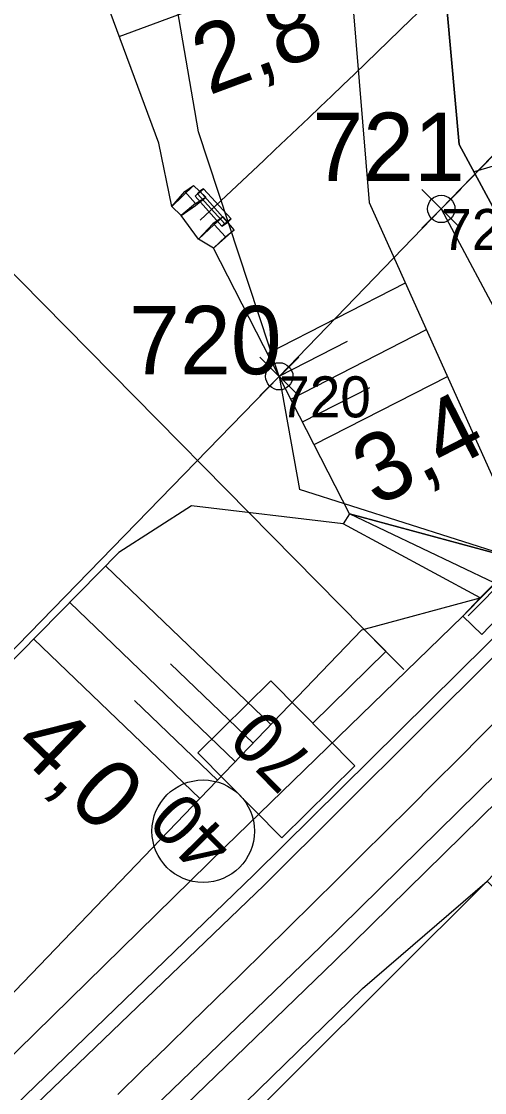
# Model space of a CAD drawing. Extents: x -800194 to -799078, y -1007177 to -1006597.
# Drawn here: x -799442.55 to -799428.99, y -1006906.14 to -1006874.78 of the extents above; entities that cross this region are included whole.
import ezdxf

# ---------------------------------------------------------------- set-up
doc = ezdxf.new("R2010")
doc.units = 0
for name, color, linetype in [('02_Osa_koleje', 7, 'Continuous'), ('Obvod stavby', 7, 'Continuous'), ('Vrstva 12', 7, 'Continuous'), ('Vrstva 17', 7, 'Continuous'), ('Vrstva 18', 7, 'Continuous'), ('Vrstva 23', 7, 'Continuous'), ('Vrstva 4', 7, 'Continuous'), ('Vrstva 47', 7, 'Continuous'), ('Vrstva 48', 7, 'Continuous'), ('Vrstva 49', 7, 'Continuous'), ('Vrstva 5', 7, 'Continuous'), ('Vrstva 50', 7, 'Continuous'), ('Vrstva 53', 7, 'Continuous'), ('Vrstva 55', 7, 'Continuous'), ('Vrstva 56', 7, 'Continuous'), ('Vrstva 60', 7, 'Continuous')]:
    doc.layers.add(name, color=color, linetype=linetype)

msp = doc.modelspace()

# ---------------------------------------------------------------- linework, layer by layer
at = {"layer": '02_Osa_koleje'}
msp.add_lwpolyline([(-799428.348, -1006894.948), (-799429.054, -1006895.657), (-799429.76, -1006896.365), (-799430.467, -1006897.072), (-799431.174, -1006897.779), (-799431.883, -1006898.484), (-799432.592, -1006899.19), (-799433.302, -1006899.894), (-799434.012, -1006900.598), (-799434.724, -1006901.3), (-799435.436, -1006902.002), (-799436.149, -1006902.703), (-799436.864, -1006903.403), (-799437.579, -1006904.102), (-799438.295, -1006904.8), (-799439.012, -1006905.497), (-799439.73, -1006906.193)], dxfattribs=at)
at = {"layer": 'Obvod stavby'}
for p, q in [((-799430.826, -1006880.836), (-799429.694, -1006879.704)), ((-799430.826, -1006879.704), (-799429.694, -1006880.836)), ((-799435.566, -1006885.736), (-799434.434, -1006884.604)), ((-799435.566, -1006884.604), (-799434.434, -1006885.736))]:
    msp.add_line(p, q, dxfattribs=at)
msp.add_lwpolyline([(-799559.64, -1006968.48), (-799519.68, -1006952.01), (-799500.87, -1006940.41), (-799496.64, -1006937.8), (-799494.85, -1006936.7), (-799484.52, -1006930.32), (-799457.99, -1006908.8), (-799435, -1006885.17), (-799430.26, -1006880.27), (-799425.53, -1006875.38), (-799422.55, -1006864.36), (-799416.748, -1006858.798), (-799395.763, -1006879.374), (-799413.75, -1006898.23), (-799418.41, -1006902.53), (-799423.07, -1006906.83), (-799433.4, -1006916.39), (-799469.5, -1006946.86), (-799487.22, -1006958.47), (-799495.25, -1006963.74), (-799521.98, -1006977.8), (-799546.71, -1006987.83)], dxfattribs=at)
for centre in [(-799430.26, -1006880.27), (-799435, -1006885.17)]:
    msp.add_circle(centre, 0.4, dxfattribs=at)
at = {"layer": 'Vrstva 12'}
for p, q in [((-799437.769, -1006879.761), (-799437.512, -1006879.586)), ((-799437.452, -1006880.113), (-799437.147, -1006879.929)), ((-799436.644, -1006880.497), (-799436.908, -1006880.728)), ((-799436.578, -1006881.084), (-799436.322, -1006880.878))]:
    msp.add_line(p, q, dxfattribs=at)
for points in [[(-799437.876, -1006880.464), (-799437.451, -1006880.166), (-799437.147, -1006879.929), (-799437.512, -1006879.586), (-799438.146, -1006880.193)], [(-799437.876, -1006880.464), (-799438.146, -1006880.193), (-799437.769, -1006879.761), (-799437.452, -1006880.113), (-799437.876, -1006880.464)], [(-799436.923, -1006881.42), (-799436.322, -1006880.878), (-799436.644, -1006880.497), (-799436.942, -1006880.704), (-799437.363, -1006881.152)], [(-799437.363, -1006881.152), (-799436.908, -1006880.728), (-799436.578, -1006881.084), (-799436.923, -1006881.42), (-799437.363, -1006881.152)]]:
    msp.add_lwpolyline(points, dxfattribs=at)
at = {"layer": 'Vrstva 17'}
msp.add_line((-799429.476, -1006892.183), (-799417.039, -1006879.551), dxfattribs=at)
at = {"layer": 'Vrstva 18'}
msp.add_line((-799429.125, -1006891.656), (-799433.133, -1006889.484), dxfattribs=at)
for points in [[(-799429.627, -1006892.19), (-799429.629, -1006892.192), (-799429.125, -1006891.656), (-799428.698, -1006891.23), (-799418.02, -1006880.424), (-799417.6, -1006879.987), (-799417.085, -1006879.46), (-799417.085, -1006879.46)], [(-799429.07, -1006892.727), (-799423.479, -1006886.901), (-799416.56, -1006880.007), (-799417.085, -1006879.46), (-799429.627, -1006892.19), (-799429.07, -1006892.727)], [(-799428.698, -1006891.23), (-799432.944, -1006889.197), (-799433.133, -1006889.484)], [(-799432.944, -1006889.197), (-799427.892, -1006890.566), (-799428.698, -1006891.23)], [(-799429.07, -1006892.727), (-799429.629, -1006892.192)]]:
    msp.add_lwpolyline(points, dxfattribs=at)
at = {"layer": 'Vrstva 23'}
for p, q in [((-799437.219, -1006879.681), (-799436.41, -1006880.559)), ((-799436.679, -1006880.778), (-799437.467, -1006879.896)), ((-799437.399, -1006879.826), (-799436.594, -1006880.708)), ((-799437.328, -1006879.75), (-799436.517, -1006880.669))]:
    msp.add_line(p, q, dxfattribs=at)
for points in [[(-799437.467, -1006879.896), (-799437.399, -1006879.826), (-799437.219, -1006879.681), (-799437.328, -1006879.75), (-799437.467, -1006879.896)], [(-799436.517, -1006880.669), (-799436.41, -1006880.559), (-799436.594, -1006880.708), (-799436.679, -1006880.778), (-799436.517, -1006880.669)]]:
    msp.add_lwpolyline(points, dxfattribs=at)
at = {"layer": 'Vrstva 4'}
for points in [[(-799510.394, -1006958.536), (-799498.027, -1006951.328), (-799477.988, -1006937.435), (-799460.33, -1006923.117), (-799451.862, -1006915.581), (-799443.604, -1006907.9), (-799435.444, -1006900.067), (-799428.64, -1006893.299), (-799422.817, -1006887.511), (-799415.998, -1006880.595), (-799408.158, -1006872.652), (-799401.02, -1006864.85)], [(-799509.248, -1006960.724), (-799497.456, -1006953.809), (-799476.495, -1006939.437), (-799458.707, -1006924.982), (-799450.277, -1006917.43), (-799441.932, -1006909.717), (-799433.783, -1006901.867), (-799426.9, -1006895.092), (-799421.037, -1006889.182), (-799414.218, -1006882.281), (-799406.443, -1006874.417), (-799398.609, -1006866.93)], [(-799511.236, -1006957.129), (-799499.236, -1006950.771), (-799498.598, -1006949.914), (-799498.679, -1006949.705), (-799496.151, -1006948.479), (-799496.251, -1006948.258), (-799490.687, -1006944.683), (-799490.497, -1006944.878), (-799488.249, -1006943.052), (-799488.105, -1006943.216), (-799486.269, -1006941.68), (-799478.997, -1006936.484), (-799474.568, -1006932.916), (-799474.237, -1006932.694), (-799461.519, -1006921.99), (-799452.935, -1006914.372), (-799444.695, -1006906.886), (-799436.579, -1006898.932), (-799429.629, -1006892.192), (-799429.07, -1006892.727), (-799423.479, -1006886.901), (-799416.56, -1006880.007), (-799417.085, -1006879.46), (-799415.349, -1006878.386)], [(-799510.726, -1006958.045), (-799497.901, -1006950.516), (-799478.36, -1006937.055), (-799461.534, -1006923.53), (-799452.128, -1006915.305), (-799443.894, -1006907.632), (-799435.739, -1006899.754), (-799428.922, -1006893.007), (-799423.223, -1006887.256), (-799416.277, -1006880.269), (-799414.896, -1006878.87)], [(-799509.087, -1006961.127), (-799497.277, -1006954.118), (-799476.183, -1006939.802), (-799458.586, -1006925.284), (-799449.914, -1006917.869), (-799441.499, -1006910.139), (-799433.371, -1006902.28), (-799426.451, -1006895.478), (-799420.657, -1006889.585), (-799413.85, -1006882.742), (-799412.388, -1006881.287)], [(-799475.489, -1006940.774), (-799457.684, -1006926.366), (-799456.318, -1006925.174), (-799455.328, -1006924.513), (-799448.961, -1006918.843), (-799440.534, -1006910.864), (-799432.566, -1006903.097), (-799428.918, -1006899.95), (-799428.131, -1006899.117), (-799425.824, -1006895.981), (-799426.173, -1006895.627), (-799420.283, -1006889.914), (-799413.647, -1006882.957), (-799413.271, -1006883.261), (-799411.693, -1006881.939)]]:
    msp.add_lwpolyline(points, dxfattribs=at)
at = {"layer": 'Vrstva 47'}
msp.add_ellipse((-799432.733, -1006875.845), major_axis=(8.482, 8.158), ratio=0.02521, start_param=4.117511, end_param=5.400082, dxfattribs=at)
at = {"layer": 'Vrstva 48'}
for p, q in [((-799439.685, -1006875.218), (-799432.976, -1006872.737)), ((-799425.83, -1006878.145), (-799429.299, -1006879.185)), ((-799435.348, -1006884.498), (-799431.312, -1006882.433)), ((-799434.665, -1006885.834), (-799430.695, -1006883.803)), ((-799435.006, -1006885.166), (-799433.005, -1006884.142)), ((-799433.981, -1006887.169), (-799430.079, -1006885.173)), ((-799434.323, -1006886.502), (-799432.355, -1006885.495)), ((-799435.25, -1006895.368), (-799440.081, -1006890.727)), ((-799436.29, -1006896.449), (-799441.134, -1006891.796)), ((-799437.329, -1006897.531), (-799442.186, -1006892.865)), ((-799435.77, -1006895.908), (-799438.189, -1006893.585)), ((-799436.809, -1006896.99), (-799439.234, -1006894.66))]:
    msp.add_line(p, q, dxfattribs=at)
at = {"layer": 'Vrstva 49'}
for points in [[(-799410.227, -1006925.149), (-799412.491, -1006911.033), (-799419.106, -1006898.668), (-799423.582, -1006889.778), (-799429.735, -1006878.378), (-799431.818, -1006855.328)], [(-799427.694, -1006890.471), (-799427.892, -1006890.566), (-799432.944, -1006889.197), (-799436.923, -1006881.42), (-799437.363, -1006881.152), (-799437.876, -1006880.464), (-799438.146, -1006880.193), (-799438.528, -1006878.348), (-799441.503, -1006870.303), (-799439.353, -1006865.427), (-799439.436, -1006859.851)], [(-799433.824, -1006862.471), (-799432.369, -1006880.085), (-799427.694, -1006890.471)], [(-799429.125, -1006891.656), (-799433.133, -1006889.484), (-799437.572, -1006888.963), (-799439.693, -1006890.332), (-799461.15, -1006912.135), (-799487.142, -1006929.222), (-799487.006, -1006931.546), (-799490.308, -1006935.771)], [(-799490.09, -1006944.145), (-799488.194, -1006942.597), (-799488.011, -1006942.815), (-799488.011, -1006942.815), (-799486.419, -1006941.508), (-799486.269, -1006941.68), (-799484.618, -1006939.109), (-799474.926, -1006932.405), (-799474.596, -1006932.171), (-799461.519, -1006921.99), (-799452.935, -1006914.372), (-799445.566, -1006906.106), (-799432.588, -1006892.596), (-799429.125, -1006891.656)], [(-799486.865, -1006949.018), (-799484.86, -1006947.727), (-799485.016, -1006947.459), (-799485.713, -1006947.881), (-799483.734, -1006946.536), (-799483.686, -1006946.569), (-799483.396, -1006947.063), (-799482.389, -1006946.51), (-799482.647, -1006946.068), (-799475.489, -1006940.774), (-799464.892, -1006933.871), (-799456.989, -1006927.138), (-799455.117, -1006925.642), (-799440.165, -1006911.165), (-799428.918, -1006899.95), (-799428.299, -1006900.544), (-799427.466, -1006899.73), (-799428.131, -1006899.117), (-799426.509, -1006898.237), (-799425.17, -1006895.342)]]:
    msp.add_lwpolyline(points, dxfattribs=at)
at = {"layer": 'Vrstva 5'}
for p, q in [((-799466.989, -1006857.616), (-799431.886, -1006893.222)), ((-799431.359, -1006893.756), (-799432.413, -1006892.688)), ((-799431.886, -1006893.222), (-799434.022, -1006895.328))]:
    msp.add_line(p, q, dxfattribs=at)
msp.add_lwpolyline([(-799435.251, -1006894.082), (-799432.794, -1006896.574), (-799434.93, -1006898.681), (-799437.387, -1006896.188)], close=True, dxfattribs=at)
msp.add_circle((-799437.227, -1006898.487), 1.5, dxfattribs=at)
at = {"layer": 'Vrstva 50'}
for points in [[(-799431.818, -1006855.328), (-799429.735, -1006878.378), (-799423.582, -1006889.778), (-799419.106, -1006898.668), (-799412.491, -1006911.033), (-799410.227, -1006925.149)], [(-799433.824, -1006862.471), (-799432.369, -1006880.085), (-799427.694, -1006890.471), (-799424.101, -1006893.992), (-799424.223, -1006894.144), (-799421.688, -1006901.262), (-799414.969, -1006911.36), (-799413.387, -1006925.296)]]:
    msp.add_lwpolyline(points, dxfattribs=at)
at = {"layer": 'Vrstva 53'}
msp.add_lwpolyline([(-799559.64, -1006968.48), (-799519.68, -1006952.01), (-799500.87, -1006940.41), (-799496.64, -1006937.8), (-799494.85, -1006936.7), (-799484.519, -1006930.319), (-799457.99, -1006908.8), (-799435, -1006885.17), (-799430.26, -1006880.27), (-799425.53, -1006875.38), (-799422.55, -1006864.36), (-799390.88, -1006834), (-799358.35, -1006806.65), (-799352.29, -1006801.56), (-799330.91, -1006783.58), (-799314.235, -1006766.649)], dxfattribs=at)
at = {"layer": 'Vrstva 55'}
for p, q in [((-799425.53, -1006875.38), (-799430.26, -1006880.27)), ((-799430.26, -1006880.27), (-799435, -1006885.17)), ((-799430.26, -1006880.27), (-799425.87, -1006888.52))]:
    msp.add_line(p, q, dxfattribs=at)
for points in [[(-799435, -1006885.17), (-799437.37, -1006878.01), (-799439.06, -1006868.14)], [(-799494.85, -1006936.7), (-799484.52, -1006930.32), (-799457.99, -1006908.8), (-799435, -1006885.17)]]:
    msp.add_lwpolyline(points, dxfattribs=at)
at = {"layer": 'Vrstva 56'}
for p in [(-799435, -1006885.17), (-799427.92, -1006890.55)]:
    msp.add_line(p, (-799434.41, -1006888.48), dxfattribs=at)
at = {"layer": 'Vrstva 60'}
for p, q in [((-799430.26, -1006880.27), (-799430.26, -1006880.27)), ((-799435, -1006885.17), (-799435, -1006885.17))]:
    msp.add_line(p, q, dxfattribs=at)

# ---------------------------------------------------------------- texts
at = {"layer": 'Obvod stavby'}
for s, p in [('721', (-799434.036, -1006879.45)), ('720', (-799439.395, -1006885.108))]:
    msp.add_text(s, height=2, rotation=360, dxfattribs=at).set_placement(p)
at = {"layer": 'Vrstva 48'}
for s, rotation, p in [('2,8', 20.2941, (-799437.062, -1006876.949)), ('3,4', 27.096, (-799432.164, -1006889.01)), ('4,0', 316.1506, (-799442.863, -1006896.053))]:
    msp.add_text(s, height=2, rotation=rotation, dxfattribs=at).set_placement(p)
at = {"layer": 'Vrstva 5'}
for s, p in [('70', (-799433.907, -1006896.414)), ('40', (-799436.265, -1006898.822))]:
    msp.add_text(s, height=1.5, rotation=134.5927, dxfattribs=at).set_placement(p)
at = {"layer": 'Vrstva 60'}
for s, p in [('721', (-799430.26, -1006881.47)), ('720', (-799435, -1006886.37))]:
    msp.add_text(s, height=1.2, dxfattribs=at).set_placement(p)

doc.saveas('drawing.dxf')
